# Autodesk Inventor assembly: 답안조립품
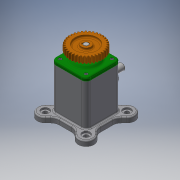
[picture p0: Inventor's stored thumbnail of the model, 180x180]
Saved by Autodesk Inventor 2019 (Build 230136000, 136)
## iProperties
Created: 2021-01
Part Number: 답안조립품
Material: 일반
Document SubType Name: Assembly
Designer: 3dpro10
Author: 3dpro10
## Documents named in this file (11)
- C:\Users\3dpro10\Desktop\710114V1012\답안조립품.iam
- C:\Users\3dpro10\Desktop\710114V1012\본체.ipt
- C:\Users\3dpro10\Desktop\710114V1012\베어링 6203.ipt
- C:\Users\3dpro10\Desktop\710114V1012\볼트 M4.ipt
- C:\Users\3dpro10\Desktop\710114V1012\부시.ipt
- C:\Users\3dpro10\Desktop\710114V1012\스퍼기어.ipt
- C:\Users\3dpro10\Desktop\710114V1012\슬라이더.ipt
- C:\Users\3dpro10\Desktop\710114V1012\오일 실.ipt
- C:\Users\3dpro10\Desktop\710114V1012\커버.ipt
- C:\Users\3dpro10\Desktop\710114V1012\키 4 x 4 x 14.ipt
- C:\Users\3dpro10\Desktop\710114V1012\편심축.ipt
